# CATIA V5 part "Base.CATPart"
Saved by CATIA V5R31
Part number: Part1
Bounding box of the stored display mesh (mm): x -50 to 50, y -25 to 25, z 0 to 50
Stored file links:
  D:\PROJECTS\Project 2021\US EDITION\CATIA V5 6R 2021\Resources\Part Files\c12_catia_v5_6r2021_prt\c12_catia_v5-6r2021 figr_12-12\Base.CATPart
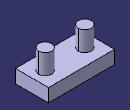
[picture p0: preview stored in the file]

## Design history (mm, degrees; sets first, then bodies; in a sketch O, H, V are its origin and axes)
Body1 (main body)
  Sketch1 on xy-plane, origin (0, 0, 0), H (1, 0, 0), V (0, 1, 0)
    line L1 (50, 25) -> (50, -25)
    line L2 (50, -25) -> (-50, -25)
    line L3 (-50, -25) -> (-50, 25)
    line L4 (-50, 25) -> (50, 25)
    circle A1 centre (-30, 0) radius 10
    point P5 (-30, 0)
    circle A2 centre (30, 0) radius 10
    length L2 = 100
    length L1 = 50
    radius A1 = 10
    distance P5 V = 30
    vertical: L1 V, L3 V
    horizontal: L2 H, L4 H
    equidistance: L1 L3 O, L2 L4 O
    coincidence: P5 H
    symmetry: A1 A2 V
  MultiPad1: profile Sketch1, domains (length 20; length 50; length 50)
